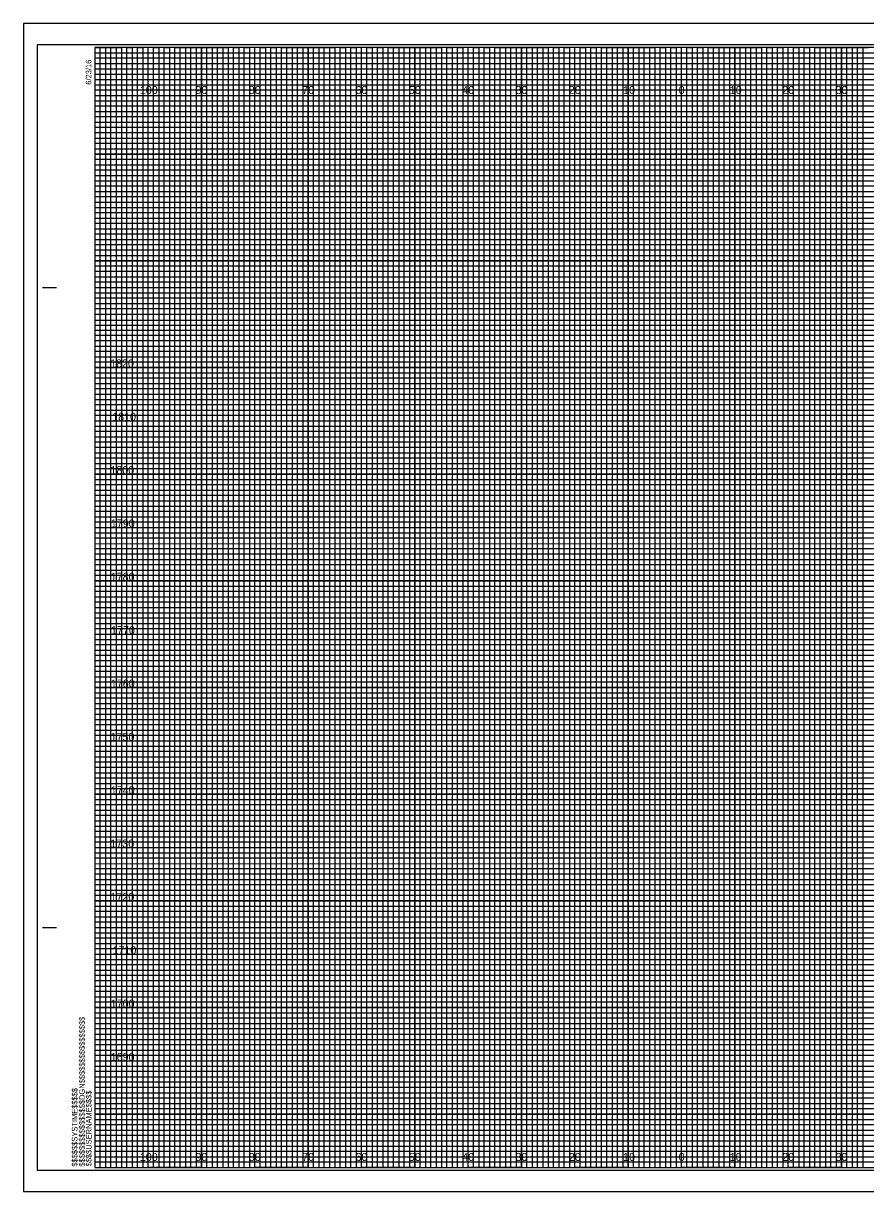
# Model space of a CAD drawing. Extents: x -419 to 4739, y -630 to 13534.
# Drawn here: x 839.6 to 997.5, y 219 to 438 of the extents above; entities that cross this region are included whole.
import ezdxf

# ---------------------------------------------------------------- set-up
doc = ezdxf.new("R2010")
doc.units = 0
for name, color, linetype in [('Old_Level_62', 7, 'Continuous'), ('Pattern 1', 7, 'Continuous'), ('Pattern 18', 7, 'Continuous'), ('Pattern 4', 7, 'Continuous'), ('Pattern 5', 7, 'Continuous'), ('Prop Dimension', 7, 'Continuous'), ('Prop Horizontal Alignment', 7, 'Continuous'), ('Raster_Level_0', 7, 'Continuous'), ('Scratch_Level_0', 7, 'Continuous'), ('Scratch_Level_3', 7, 'Continuous'), ('Scratch_Level_5', 7, 'Continuous')]:
    doc.layers.add(name, color=color, linetype=linetype)

msp = doc.modelspace()

# ---------------------------------------------------------------- linework, layer by layer
at = {"layer": 'Old_Level_62'}
for p, q in [((843.25, 388.49), (845.75, 388.49)), ((843.35, 388.49), (845.85, 388.49)), ((843.25, 268.49), (845.75, 268.49)), ((843.35, 268.49), (845.85, 268.49)), ((853.05, 223.49), (853.05, 223.49)), ((853.05, 223.49), (853.05, 223.49)), ((853.05, 223.49), (853.05, 223.49)), ((853.05, 223.49), (853.05, 223.49)), ((853.05, 223.49), (853.05, 223.49)), ((853.05, 223.49), (853.05, 223.49)), ((853.05, 223.49), (853.05, 223.49))]:
    msp.add_line(p, q, dxfattribs=at)
msp.add_lwpolyline([(1173.05, 433.49), (853.05, 433.49), (853.05, 223.49), (1173.05, 223.49)], close=True, dxfattribs=at)
at = {"layer": 'Pattern 18'}
msp.add_lwpolyline([(839.65, 218.99), (1176.35, 218.99), (1176.35, 437.99), (839.65, 437.99)], close=True, dxfattribs=at)
at = {"layer": 'Pattern 4'}
for p, q in [((853.05, 432.49), (1113.05, 432.49)), ((1113.05, 431.47), (853.05, 431.47)), ((853.05, 431.47), (853.05, 430.49)), ((853.05, 430.49), (1113.05, 430.49)), ((1113.05, 429.38), (853.05, 429.38)), ((853.05, 429.38), (853.05, 427.49)), ((853.05, 427.49), (1173.05, 427.49))]:
    msp.add_line(p, q, dxfattribs=at)
for points in [[(853.05, 426.49), (1123.05, 426.49), (1173.05, 426.49), (1173.05, 425.49), (853.05, 425.49)], [(853.05, 424.49), (1173.05, 424.49), (1173.05, 422.49), (853.05, 422.49)], [(853.05, 421.49), (1173.05, 421.49), (1173.05, 420.49), (853.05, 420.47)], [(853.05, 419.49), (1173.05, 419.49), (1173.05, 417.49), (853.05, 417.49)], [(853.05, 416.49), (1173.05, 416.49), (1173.05, 415.49), (853.05, 415.49)], [(853.05, 414.49), (1173.05, 414.49), (1173.05, 412.49), (853.05, 412.49)], [(853.05, 411.49), (1173.05, 411.49), (1173.05, 410.49), (853.05, 410.49)], [(853.05, 409.49), (1173.05, 409.49), (1173.05, 407.49), (853.05, 407.49)], [(853.05, 406.49), (1173.05, 406.49), (1173.05, 405.49), (853.05, 405.49)], [(853.05, 404.49), (1173.05, 404.49), (1173.05, 402.49), (853.05, 402.49)], [(853.05, 401.49), (1173.05, 401.49), (1173.05, 400.49), (853.05, 400.49)], [(853.05, 399.49), (1173.05, 399.49), (1173.05, 397.44), (1173.05, 396.49), (1173.05, 395.49), (853.05, 395.49)], [(853.05, 397.49), (1173.05, 397.49), (1173.05, 396.49), (853.05, 396.49)], [(853.05, 394.49), (1173.05, 394.49), (1173.05, 392.49), (853.05, 392.52)], [(853.05, 392.52), (1173.05, 392.49), (1173.05, 391.49), (853.05, 391.49)], [(853.05, 390.49), (1173.05, 390.49), (1173.05, 389.49), (853.05, 389.49)], [(853.05, 387.49), (1173.05, 387.49), (1173.05, 386.49), (853.05, 386.49)], [(853.05, 385.49), (1173.05, 385.49), (1173.05, 384.49), (853.05, 384.49)], [(852.98, 382.38), (1173.05, 382.38), (1173.05, 381.37), (852.98, 381.37)], [(853.05, 380.49), (1173.05, 380.49), (1173.05, 379.49), (853.05, 379.49)], [(853.05, 377.49), (1173.05, 377.49), (1173.05, 376.49), (853.05, 376.49)], [(853.05, 375.49), (1173.05, 375.49), (1173.05, 374.49), (853.05, 374.49)], [(853.05, 372.49), (1173.05, 372.49), (1173.05, 371.49), (853.05, 371.49)], [(853.05, 370.49), (1173.05, 370.49), (1173.05, 369.49), (853.05, 369.49)], [(853.05, 367.49), (1173.05, 367.49), (1173.05, 366.49), (853.05, 366.49)], [(853.05, 365.49), (1173.05, 365.49), (1173.05, 364.49), (853.05, 364.49)], [(853.05, 362.49), (1173.05, 362.49), (1173.04, 361.47), (853.05, 361.49)], [(853.05, 360.49), (1173.05, 360.49), (1173.05, 359.49), (853.05, 359.49)], [(853.05, 357.49), (1173.05, 357.49), (1173.05, 356.49), (853.05, 356.49)], [(853.05, 355.49), (1173.05, 355.49), (1173.05, 354.49), (853.05, 354.49)], [(853.05, 352.49), (1173.05, 352.49), (1173.05, 351.49), (853.05, 351.49)], [(853.05, 350.49), (1173.05, 350.49), (1173.05, 349.49), (853.05, 349.49)], [(853.05, 347.49), (1173.05, 347.49), (1173.05, 346.49), (853.05, 346.49)], [(853.05, 345.49), (1173.05, 345.49), (1173.05, 344.49), (853.05, 344.49)], [(853.05, 342.49), (1173.05, 342.49), (1173.05, 341.49), (853.05, 341.49)], [(853.05, 340.48), (1173.12, 340.4), (1173.05, 339.49), (853.05, 339.49)], [(853.05, 337.49), (1173.05, 337.49), (1173.05, 336.49), (853.05, 336.49)], [(853.05, 335.49), (1173.05, 335.49), (1173.05, 334.49), (853.05, 334.49)], [(853.05, 332.49), (1173.05, 332.49), (1173.05, 331.49), (853.05, 331.49)], [(853.05, 330.49), (1173.05, 330.49), (1173.05, 329.49), (853.05, 329.49)], [(853.05, 327.49), (1173.05, 327.49), (1173.05, 326.49), (853.05, 326.49)], [(853.05, 325.49), (1173.05, 325.49), (1173.05, 324.49), (853.05, 324.49)], [(853.05, 322.49), (1173.05, 322.49), (1173.05, 321.49), (853.05, 321.49)], [(853.05, 320.49), (1173.05, 320.49), (1173.05, 319.49), (853.05, 319.49)], [(853.05, 317.49), (1173.05, 317.49), (1173.05, 316.49), (853.05, 316.49)], [(853.05, 315.49), (1173.05, 315.49), (1173.05, 314.49), (853.05, 314.49)], [(853.05, 312.49), (1173.05, 312.49), (1173.05, 311.49), (853.05, 311.49)], [(853.05, 310.49), (1173.05, 310.49), (1173.05, 309.49), (853.05, 309.49)], [(853.05, 307.49), (1173.05, 307.49), (1173.05, 306.49), (853.05, 306.49)], [(853.05, 305.49), (1173.05, 305.49), (1173.05, 304.49), (853.05, 304.49)], [(853.05, 302.49), (1173.05, 302.49), (1173.04, 301.47), (853.05, 301.49)], [(853.05, 300.49), (1173.05, 300.49), (1173.05, 299.49), (853.05, 299.49)], [(853.05, 297.49), (1173.05, 297.49), (1173.05, 296.49), (853.05, 296.49)], [(853.05, 295.49), (1173.05, 295.49), (1173.05, 294.49), (853.05, 294.49)], [(853.05, 292.49), (1173.05, 292.49), (1173.05, 291.49), (853.05, 291.49)], [(853.05, 290.49), (1173.05, 290.49), (1173.05, 289.49), (853.05, 289.49)], [(853.05, 287.49), (1173.05, 287.49), (1173.05, 286.49), (853.05, 286.49)], [(853.05, 285.49), (1173.05, 285.49), (1173.05, 284.49), (853.05, 284.49)], [(853.05, 282.49), (1173.05, 282.49), (1173.05, 281.49), (853.05, 281.49)], [(853.05, 280.48), (1173.12, 280.4), (1173.05, 279.49), (853.05, 279.49)], [(853.05, 277.49), (1173.05, 277.49), (1173.05, 276.49), (853.05, 276.49)], [(853.05, 275.49), (1173.05, 275.49), (1173.05, 274.49), (853.05, 274.49)], [(853.05, 272.49), (1173.05, 272.49), (1173.05, 271.49), (853.05, 271.49)], [(853.05, 270.49), (1173.05, 270.49), (1173.05, 269.49), (853.05, 269.49)], [(853.05, 267.49), (1173.05, 267.49), (1173.05, 266.49), (853.05, 266.49)], [(853.05, 265.49), (1173.05, 265.49), (1173.05, 264.49), (853.05, 264.49)], [(853.05, 262.49), (1173.05, 262.49), (1173.05, 261.49), (853.05, 261.49)], [(853.05, 260.49), (1173.05, 260.49), (1173.05, 259.49), (853.05, 259.49)], [(853.05, 257.49), (1173.05, 257.49), (1173.05, 256.49), (853.05, 256.49)], [(853.05, 255.49), (1173.05, 255.49), (1173.05, 254.49), (853.05, 254.49)], [(853.05, 252.49), (1173.05, 252.49), (1173.05, 251.49), (853.05, 251.49)], [(853.05, 250.49), (1173.05, 250.49), (1173.05, 249.49), (853.05, 249.49)], [(853.05, 247.49), (1173.05, 247.49), (1173.05, 246.49), (853.05, 246.49)], [(853.05, 245.49), (1173.05, 245.49), (1173.05, 244.49), (853.05, 244.49)], [(853.05, 242.49), (1173.05, 242.49), (1173.05, 241.49), (853.05, 241.49)], [(853.05, 240.49), (1173.05, 240.49), (1173.05, 239.49), (853.05, 239.49)], [(853.05, 237.49), (1173.05, 237.49), (1173.05, 236.49), (853.05, 236.49)], [(853.05, 235.49), (1173.05, 235.49), (1173.05, 234.49), (853.05, 234.49)], [(853.05, 232.49), (1173.05, 232.49), (1173.05, 231.49), (853.05, 231.49)], [(853.05, 230.49), (1173.05, 230.49), (1173.05, 229.49), (853.05, 229.49)], [(853.05, 227.49), (1173.05, 227.49), (1173.05, 226.49), (853.05, 226.49)], [(853.05, 225.49), (1173.05, 225.49), (1173.05, 224.49), (853.05, 224.49)]]:
    msp.add_lwpolyline(points, dxfattribs=at)
at = {"layer": 'Pattern 5'}
for p, q in [((1176.35, 437.99), (839.65, 437.99)), ((839.65, 437.99), (839.65, 218.99)), ((839.65, 218.99), (1176.35, 218.99))]:
    msp.add_line(p, q, dxfattribs=at)
at = {"layer": 'Prop Dimension'}
for points in [[(853.05, 223.49), (854.05, 223.49), (854.05, 433.49), (855.05, 433.49), (855.05, 223.49)], [(855.05, 223.49), (856.05, 223.49), (856.05, 433.49), (857.05, 433.49), (857.05, 223.49)], [(858.05, 223.49), (859.05, 223.49), (859.05, 433.49), (860.05, 433.49), (860.05, 223.49)], [(860.05, 223.49), (861.05, 223.49), (861.05, 433.49), (862.05, 433.49), (862.05, 223.49)], [(863.05, 223.49), (864.05, 223.49), (864.05, 433.49), (865.05, 433.49), (865.05, 223.49)], [(865.05, 223.49), (866.05, 223.49), (866.05, 433.49), (867.05, 433.49), (867.05, 223.49)], [(868.05, 223.49), (869.05, 223.49), (869.05, 433.49), (870.05, 433.49), (870.05, 223.49)], [(870.05, 223.49), (871.05, 223.49), (871.05, 433.49), (872.05, 433.49), (872.05, 223.49)], [(873.05, 223.49), (874.05, 223.49), (874.05, 433.49), (875.05, 433.49), (875.05, 223.49)], [(875.05, 223.49), (876.05, 223.49), (876.05, 433.49), (877.05, 433.49), (877.05, 223.49)], [(878.05, 223.49), (879.05, 223.49), (879.05, 433.49), (880.05, 433.49), (880.05, 223.49)], [(880.05, 223.49), (881.05, 223.49), (881.05, 433.49), (882.05, 433.49), (882.05, 223.49)], [(883.05, 223.49), (884.05, 223.49), (884.05, 433.49), (885.05, 433.49), (885.05, 223.49)], [(885.05, 223.49), (886.05, 223.49), (886.05, 433.49), (887.05, 433.49), (887.05, 223.49)], [(888.05, 223.49), (889.05, 223.49), (889.05, 433.49), (890.05, 433.49), (890.05, 223.49)], [(890.05, 223.49), (891.05, 223.49), (891.05, 433.49), (892.05, 433.49), (892.05, 223.49)], [(893.05, 223.49), (894.05, 223.49), (894.05, 433.49), (895.05, 433.49), (895.05, 223.49)], [(895.05, 223.49), (896.05, 223.49), (896.05, 433.49), (897.05, 433.49), (897.05, 223.49)], [(898.05, 223.49), (899.05, 223.49), (899.05, 433.49), (900.05, 433.49), (900.05, 223.49)], [(900.05, 223.49), (901.05, 223.49), (901.05, 433.49), (902.05, 433.49), (902.05, 223.49)], [(903.05, 223.49), (904.05, 223.49), (904.05, 433.49), (905.05, 433.49), (905.05, 223.49)], [(905.05, 223.49), (906.05, 223.49), (906.05, 433.49), (907.05, 433.49), (907.05, 223.49)], [(908.05, 223.49), (909.05, 223.49), (909.05, 433.49), (910.05, 433.49), (910.05, 223.49)], [(910.05, 223.49), (911.05, 223.49), (911.05, 433.49), (912.05, 433.49), (912.05, 223.49)], [(913.05, 223.49), (914.05, 223.49), (914.05, 433.49), (915.05, 433.49), (915.05, 223.49)], [(915.05, 223.49), (916.05, 223.49), (916.05, 433.49), (917.05, 433.49), (917.05, 223.49)], [(918.05, 223.49), (919.05, 223.49), (919.05, 433.49), (920.05, 433.49), (920.05, 223.49)], [(920.05, 223.49), (921.05, 223.49), (921.05, 433.49), (922.05, 433.49), (922.05, 223.49)], [(923.05, 223.49), (924.05, 223.49), (924.05, 433.49), (925.05, 433.49), (925.05, 223.49)], [(925.05, 223.49), (926.05, 223.49), (926.05, 433.49), (927.05, 433.49), (927.05, 223.49)], [(928.05, 223.49), (929.05, 223.49), (929.05, 433.49), (930.05, 433.49), (930.05, 223.49)], [(930.05, 223.49), (931.05, 223.49), (931.05, 433.49), (932.05, 433.49), (932.05, 223.49)], [(933.05, 223.49), (934.05, 223.49), (934.05, 433.49), (935.05, 433.49), (935.05, 223.49)], [(935.05, 223.49), (936.05, 223.49), (936.05, 433.49), (937.05, 433.49), (937.05, 223.49)], [(938.05, 223.49), (939.05, 223.49), (939.05, 433.49), (940.05, 433.49), (940.05, 223.49)], [(940.05, 223.49), (941.05, 223.49), (941.05, 433.49), (942.05, 433.49), (942.05, 223.49)], [(943.05, 223.49), (944.05, 223.49), (944.05, 433.49), (945.05, 433.49), (945.05, 223.49)], [(945.05, 223.49), (946.05, 223.49), (946.05, 433.49), (947.05, 433.49), (947.05, 223.49)], [(948.05, 223.49), (949.05, 223.49), (949.05, 433.49), (950.05, 433.49), (950.05, 223.49)], [(950.05, 223.49), (951.05, 223.49), (951.05, 433.49), (952.05, 433.49), (952.05, 223.49)], [(953.05, 223.49), (954.05, 223.49), (954.05, 433.49), (955.05, 433.49), (955.05, 223.49)], [(955.05, 223.49), (956.05, 223.49), (956.05, 433.49), (957.05, 433.49), (957.05, 223.49)], [(958.05, 223.49), (959.05, 223.49), (959.05, 433.49), (960.05, 433.49), (960.05, 223.49)], [(960.05, 223.49), (961.05, 223.49), (961.05, 433.49), (962.05, 433.49), (962.05, 223.49)], [(963.05, 223.49), (964.05, 223.49), (964.05, 433.49), (965.05, 433.49), (965.05, 223.49)], [(965.05, 223.49), (966.05, 223.49), (966.05, 433.49), (967.05, 433.49), (967.05, 223.49)], [(968.05, 223.49), (969.05, 223.49), (969.05, 433.49), (970.05, 433.49), (970.05, 223.49)], [(970.05, 223.49), (971.05, 223.49), (971.05, 433.49), (972.05, 433.49), (972.05, 223.49)], [(973.05, 223.49), (974.05, 223.49), (974.05, 433.49), (975.05, 433.49), (975.05, 223.49)], [(975.05, 223.49), (976.05, 223.49), (976.05, 433.49), (977.05, 433.49), (977.05, 223.49)], [(978.05, 223.49), (979.05, 223.49), (979.05, 433.49), (980.05, 433.49), (980.05, 223.49)], [(980.05, 223.49), (981.05, 223.49), (981.05, 433.49), (982.05, 433.49), (982.05, 223.49)], [(983.05, 223.49), (984.05, 223.49), (984.05, 433.49), (985.05, 433.49), (985.05, 223.49)], [(985.05, 223.49), (986.05, 223.49), (986.05, 433.49), (987.05, 433.49), (987.05, 223.49)], [(988.05, 223.49), (989.05, 223.49), (989.05, 433.49), (990.05, 433.49), (990.05, 223.49)], [(990.05, 223.49), (991.05, 223.49), (991.05, 433.49), (992.05, 433.49), (992.05, 223.49)], [(993.05, 223.49), (994.05, 223.49), (994.05, 433.49), (995.05, 433.49), (995.05, 223.49)], [(995.05, 223.49), (996.05, 223.49), (996.05, 433.49), (997.05, 433.49), (997.05, 223.49)]]:
    msp.add_lwpolyline(points, dxfattribs=at)
at = {"layer": 'Prop Horizontal Alignment'}
for points in [[(853.05, 433.49), (858.05, 433.49), (858.05, 223.49), (868.05, 223.49), (868.05, 433.49), (878.05, 433.49), (878.05, 223.49), (888.05, 223.49), (888.05, 433.49), (898.05, 433.49), (898.05, 223.49), (908.05, 223.49), (908.05, 433.49), (918.05, 433.49), (918.05, 223.49), (928.05, 223.49), (928.05, 433.49), (938.05, 433.49), (938.05, 223.49), (948.05, 223.49), (948.05, 433.49), (958.05, 433.49), (958.05, 223.49), (968.05, 223.49), (968.05, 433.49), (978.05, 433.49), (978.05, 223.49), (988.05, 223.49), (988.05, 433.49), (998.05, 433.49)], [(853.05, 428.49), (1128.05, 428.49)], [(853.05, 408.49), (1173.05, 408.49), (1173.05, 418.49), (853.05, 418.49)], [(853.05, 388.49), (1173.05, 388.49), (1173.05, 398.49), (853.05, 398.49)], [(853.05, 368.49), (1173.05, 368.49), (1173.05, 378.49), (853.05, 378.49)], [(853.05, 348.49), (1173.05, 348.49), (1173.05, 358.49), (853.05, 358.49)], [(853.05, 328.49), (1173.05, 328.49), (1173.05, 338.49), (853.05, 338.49)], [(853.05, 308.49), (1173.05, 308.49), (1173.05, 318.49), (853.05, 318.49)], [(853.05, 288.49), (1173.05, 288.49), (1173.05, 298.49), (853.05, 298.49)], [(853.05, 268.49), (1173.05, 268.49), (1173.05, 278.49), (853.05, 278.49)], [(853.05, 248.49), (1173.05, 248.49), (1173.05, 258.49), (853.05, 258.49)], [(853.05, 228.49), (1173.05, 228.49), (1173.05, 238.49), (853.05, 238.49)]]:
    msp.add_lwpolyline(points, dxfattribs=at)
at = {"layer": 'Scratch_Level_0'}
for p, q in [((863.05, 223.49), (863.05, 433.49)), ((873.05, 223.49), (873.05, 433.49)), ((883.05, 223.49), (883.05, 433.49)), ((893.05, 223.49), (893.05, 433.49)), ((903.05, 223.49), (903.05, 433.49)), ((913.05, 223.49), (913.05, 433.49)), ((923.05, 223.49), (923.05, 433.49)), ((933.05, 223.49), (933.05, 433.49)), ((943.05, 223.49), (943.05, 433.49)), ((953.05, 223.49), (953.05, 433.49)), ((963.05, 223.49), (963.05, 433.49)), ((973.05, 223.49), (973.05, 433.49)), ((983.05, 223.49), (983.05, 433.49)), ((993.05, 223.49), (993.05, 433.49)), ((853.05, 423.49), (1173.05, 423.49)), ((853.05, 413.49), (1173.05, 413.49)), ((853.05, 403.49), (1173.05, 403.49)), ((853.05, 393.49), (1173.05, 393.49)), ((853.05, 383.49), (1173.05, 383.49)), ((853.05, 373.49), (1173.05, 373.49)), ((853.05, 363.49), (1173.05, 363.49)), ((853.05, 353.49), (1173.05, 353.49)), ((853.05, 343.49), (1173.05, 343.49)), ((853.05, 333.49), (1173.05, 333.49)), ((853.05, 323.49), (1173.05, 323.49)), ((853.05, 313.49), (1173.05, 313.49)), ((853.05, 303.49), (1173.05, 303.49)), ((853.05, 293.49), (1173.05, 293.49)), ((853.05, 283.49), (1173.05, 283.49)), ((853.05, 273.49), (1173.05, 273.49)), ((853.05, 263.49), (1173.05, 263.49)), ((853.05, 253.49), (1173.05, 253.49)), ((853.05, 243.49), (1173.05, 243.49)), ((853.05, 233.49), (1173.05, 233.49))]:
    msp.add_line(p, q, dxfattribs=at)
at = {"layer": 'Scratch_Level_3'}
for p, q in [((863.05, 433.49), (853.05, 433.49)), ((863.05, 223.49), (863.05, 433.49)), ((883.05, 433.49), (873.05, 433.49)), ((873.05, 433.49), (873.05, 223.49)), ((883.05, 223.49), (883.05, 433.49)), ((903.05, 433.49), (893.05, 433.49)), ((893.05, 433.49), (893.05, 223.49)), ((903.05, 223.49), (903.05, 433.49)), ((923.05, 433.49), (913.05, 433.49)), ((913.05, 433.49), (913.05, 223.49)), ((923.05, 223.49), (923.05, 433.49)), ((943.05, 433.49), (933.05, 433.49)), ((933.05, 433.49), (933.05, 223.49)), ((943.05, 223.49), (943.05, 433.49)), ((963.05, 433.49), (953.05, 433.49)), ((953.05, 433.49), (953.05, 223.49)), ((963.05, 223.49), (963.05, 433.49)), ((983.05, 433.49), (973.05, 433.49)), ((973.05, 433.49), (973.05, 223.49)), ((983.05, 223.49), (983.05, 433.49)), ((1003.05, 433.49), (993.05, 433.49)), ((993.05, 433.49), (993.05, 223.49)), ((873.05, 223.49), (863.05, 223.49)), ((893.05, 223.49), (883.05, 223.49)), ((913.05, 223.49), (903.05, 223.49)), ((933.05, 223.49), (923.05, 223.49)), ((953.05, 223.49), (943.05, 223.49)), ((973.05, 223.49), (963.05, 223.49)), ((993.05, 223.49), (983.05, 223.49))]:
    msp.add_line(p, q, dxfattribs=at)
for points in [[(853.05, 423.49), (1173.05, 423.49), (1173.05, 413.49), (853.05, 413.49)], [(853.05, 403.49), (1173.05, 403.49), (1173.05, 393.49), (853.05, 393.49)], [(853.05, 383.49), (1173.05, 383.49), (1173.05, 373.49), (853.05, 373.49)], [(853.05, 363.49), (1173.05, 363.49), (1173.05, 353.49), (853.05, 353.49)], [(853.05, 343.49), (1173.05, 343.49), (1173.05, 333.49), (853.05, 333.49)], [(853.05, 323.49), (1173.05, 323.49), (1173.05, 313.49), (853.05, 313.49)], [(853.05, 303.49), (1173.05, 303.49), (1173.05, 293.49), (853.05, 293.49)], [(853.05, 283.49), (1173.05, 283.49), (1173.05, 273.49), (853.05, 273.49)], [(853.05, 263.49), (1173.05, 263.49), (1173.05, 253.49), (853.05, 253.49)], [(853.05, 243.49), (1173.05, 243.49), (1173.05, 233.49), (853.05, 233.49)]]:
    msp.add_lwpolyline(points, dxfattribs=at)
at = {"layer": 'Scratch_Level_5'}
msp.add_lwpolyline([(842.25, 222.99), (1175.45, 222.99), (1175.45, 433.99), (842.25, 433.99)], close=True, dxfattribs=at)

# ---------------------------------------------------------------- texts
at = {"layer": 'Old_Level_62'}
for s, p in [('6/23/16', (852.4, 426.49)), ('$$$$$$$$$$$$$$$$DGN$$$$$$$$$$$$$$$$', (851.17, 223.67)), ('$$$$$$SYSTIME$$$$$', (849.79, 223.67)), ('$$$$USERNAME$$$$', (852.43, 223.72))]:
    msp.add_text(s, height=1.05, rotation=90, dxfattribs=at).set_placement(p)
at = {"layer": 'Pattern 1'}
for s, p in [('1820', (855.92, 373.49)), ('1810', (856.3, 363.49)), ('1800', (855.97, 353.49)), ('1790', (856.05, 343.49)), ('1780', (856.03, 333.49)), ('1770', (856.09, 323.49)), ('1760', (856.05, 313.49)), ('1750', (856, 303.49)), ('1740', (856.05, 293.49)), ('1730', (855.97, 283.49)), ('1720', (855.98, 273.49)), ('1710', (856.36, 263.49)), ('1700', (856.03, 253.49)), ('1690', (856.02, 243.49))]:
    msp.add_text(s, height=1.5, dxfattribs=at).set_placement(p)
at = {"layer": 'Raster_Level_0'}
for s, p in [('100', (861.49, 424.74)), ('90', (871.91, 424.74)), ('80', (881.91, 424.74)), ('70', (891.91, 424.74)), ('60', (901.91, 424.74)), ('50', (911.91, 424.74)), ('40', (921.91, 424.74)), ('30', (931.91, 424.74)), ('20', (941.91, 424.74)), ('10', (952.08, 424.74)), ('0', (962.5, 424.74)), ('0', (962.5, 424.74)), ('10', (972.08, 424.74)), ('20', (981.91, 424.74)), ('30', (991.91, 424.74)), ('100', (861.49, 224.74)), ('90', (871.91, 224.74)), ('80', (881.91, 224.74)), ('70', (891.91, 224.74)), ('60', (901.91, 224.74)), ('50', (911.91, 224.74)), ('40', (921.91, 224.74)), ('30', (931.91, 224.74)), ('20', (941.91, 224.74)), ('10', (952.08, 224.74)), ('0', (962.5, 224.74)), ('0', (962.5, 224.74)), ('10', (972.08, 224.74)), ('20', (981.91, 224.74)), ('30', (991.91, 224.74))]:
    msp.add_text(s, height=1.5, dxfattribs=at).set_placement(p)

doc.saveas('drawing.dxf')
